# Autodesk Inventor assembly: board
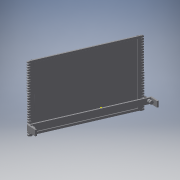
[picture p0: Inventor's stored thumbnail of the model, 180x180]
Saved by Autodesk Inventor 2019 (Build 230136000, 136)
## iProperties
Created: 2019-11
Part Number: board
Document SubType Name: Assembly
Designer: PRADYUMNA
Author: PRADYUMNA
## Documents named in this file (8)
- C:\Users\Sangeetha Jathar\Desktop\New folder\bhanu\board.iam
- C:\Users\Sangeetha Jathar\Desktop\New folder\bhanu\boardf.ipt
- C:\Users\Sangeetha Jathar\Desktop\New folder\bhanu\rack.ipt
- C:\Users\Sangeetha Jathar\Desktop\New folder\bhanu\gear.ipt
- C:\Users\Sangeetha Jathar\Desktop\New folder\bhanu\Lchannel.ipt
- C:\Users\Sangeetha Jathar\Desktop\New folder\bhanu\motor.ipt
- C:\Users\Sangeetha Jathar\Desktop\New folder\bhanu\jvsuv.ipt
- C:\Users\Sangeetha Jathar\Desktop\New folder\cchannel.ipt
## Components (13 placed, 7 different names)
1. boardf:2 — Mate:1, Mate:14, Mate:15, Mate:16, Mate:20, Mate:21, Mate:22, Mate:23, Mate:24, Mate:25, Mate:26
2. rack:2 — Mate:1, Mate:16, Mate:27, Mate:28, Mate:29, Mate:32
3. gear:1 — Mate:13, Mate:32
4. gear:2 — Mate:9, Mate:10
5. Lchannel:1 — Mate:3, Mate:4, Mate:5, Mate:6, Mate:14, Mate:15
6. motor:1 — Mate:3, Mate:4, Mate:7, Mate:8
7. motor:2 — Mate:5, Mate:6, Mate:11, Mate:12
8. jvsuv:1 — Mate:7, Mate:8, Mate:9, Mate:10
9. jvsuv:2 — Mate:11, Mate:12, Mate:13
10. cchannel:1 — Mate:20, Mate:21, Mate:22, Mate:27, Mate:28, Mate:29
11. cchannel:2 — Mate:23, Mate:24, Mate:25, Mate:26, Mate:30, Mate:31
12. rack:3
13. rack:4 — Mate:30, Mate:31
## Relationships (28: Mate 28)
- Mate:1: boardf:2 ↔ rack:2
- Mate:3: Lchannel:1 ↔ motor:1
- Mate:4: Lchannel:1 ↔ motor:1
- Mate:5: Lchannel:1 ↔ motor:2
- Mate:6: Lchannel:1 ↔ motor:2
- Mate:7: motor:1 ↔ jvsuv:1
- Mate:8: motor:1 ↔ jvsuv:1
- Mate:9: gear:2 ↔ jvsuv:1
- Mate:10: gear:2 ↔ jvsuv:1
- Mate:11: motor:2 ↔ jvsuv:2
- Mate:12: motor:2 ↔ jvsuv:2
- Mate:13: gear:1 ↔ jvsuv:2
- Mate:14: boardf:2 ↔ Lchannel:1
- Mate:15: boardf:2 ↔ Lchannel:1
- Mate:16: boardf:2 ↔ rack:2
- Mate:20: boardf:2 ↔ cchannel:1
- Mate:21: boardf:2 ↔ cchannel:1
- Mate:22: boardf:2 ↔ cchannel:1
- Mate:23: boardf:2 ↔ cchannel:2
- Mate:24: boardf:2 ↔ cchannel:2
- Mate:25: boardf:2 ↔ cchannel:2
- Mate:26: boardf:2 ↔ cchannel:2
- Mate:27: rack:2 ↔ cchannel:1
- Mate:28: rack:2 ↔ cchannel:1
- Mate:29: rack:2 ↔ cchannel:1
- Mate:30: cchannel:2 ↔ rack:4
- Mate:31: cchannel:2 ↔ rack:4
- Mate:32: rack:2 ↔ gear:1
